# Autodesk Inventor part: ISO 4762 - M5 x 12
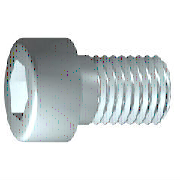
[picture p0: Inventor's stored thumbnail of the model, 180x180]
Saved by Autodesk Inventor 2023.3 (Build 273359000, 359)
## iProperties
Created: 2022-02
Part Number: ISO 4762 - M5 x 12
Material: Acier inoxydable 440C
Description: Vis cylindrique à six pans creux
Document SubType Name: Modeling
Standard: ISO 4762
Designer: Thier
Standard Revision: Fourth edition 2004-03-01
Standards Organization: ISO
Language: fr-FR
Size Designation: M5 x 12
Categories: <MemberInstance><Categories><Category DisplayName="Visserie" InternalName="e4da775c-781d-43d5-af7c-5136215cf5a6" Mnemonic="FSTN"><Category DisplayName="Vis" Int
Density: 7.75 g/cm^3
Appearance: Semi-poli
IsCustomPart: 0
Author: Thier
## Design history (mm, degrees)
sketch "Esquisse1"
  geometry: L1 (-1.167, 0)-(12, 0); L2 (12, 0)-(12, 2.5); L3 (12, 2.5)-(2, 2.5); L4 (2, 2.5)-(1.509, 2.5); L5 (1.509, 2.5)-(0, 2.5); L6 (0, 2.5)-(0, 4.25); L7 (0, 4.25)-(-5, 4.25); L8 (-5, 4.25)-(-5, 2.309); L9 (-5, 2.309)-(-2.5, 2.309); L10 (-2.5, 2.309)-(-1.167, 0); L11 (-8.4, 0)-(15.4, 0) reference; L12 (0, -0.85)-(0, 5.1) reference; L13 (2, 2.5)-(0, 2.5)
  constraints: 22 end point, 6 parallel, 2 collinear, 2 perpendicular, 1 horizontal, 1 point on line
  dimensions: "d1" = 10 distance from line of L3.end L2 (= GEL); "d2" = 0.49086 distance of L4.end L3.end (computed from GAL); "d3" = 5 distance between parallel lines of L8 L6 (= KOH); "d4" = 2.5 distance of L8.end L9.end (= INTI); "d5" = 60 deg angle of L10 L1; "d6" = 5 diameter of L3 L1 (= GD); "d7" = 5 diameter of L5 L1 (= BDM); "d8" = 4.6188 diameter of L9 L1 (= 1.1547 x SW); "d9" = 8.5 diameter of L7 L1 (= KOD); "d26" = 12 distance between parallel lines of L12 L2 (= NLG)
revolve "Corps" sketch "Esquisse1" stored, may be unused: angle "d10" = 90 deg
sketch "Esquisse2"
  geometry: L1 (0, -5.95)-(0, 5.95) reference; L2 (-5.95, 0)-(5.95, 0) reference; L3 (2.309, 0)-(1.155, -2); L4 (1.155, -2)-(-1.155, -2); L5 (-1.155, -2)-(-2.309, 0); L6 (-2.309, 0)-(-1.155, 2); L7 (-1.155, 2)-(1.155, 2); L8 (1.155, 2)-(2.309, 0); 2 further points
  constraints: 12 end point, 1 coincident, 1 horizontal alignment, 1 point on line, 12 other
extrude "Rainure" join sketch "Esquisse2" stored distance "d11" = 10; taper "d12" = 0 deg
workplane "Work Plane1"
fillet "Fillet2" dims "d30" = 0.1 (= R)
body "Solid1"
fillet "Congé1" dims "d17" = 0.5 (= RR)
feature "Filetage" dims "d13" = 10 (= GEL), "d14" = 0
chamfer "Chanfrein1" distance "d15" = 0.49076 (= -0.5 x SPD + 0.5 x GD); stored, may be unused: second distance "d16" = 0.49076 (= GUL), angle "d27" = 45 deg
other parameters: "GD" = 5 [user parameter; used in 2 equation terms], "NLG" = 12 [user parameter; used in 1 equation term], "GEL" = 10 [user parameter; used in 2 equation terms], "KOD" = 8.5 [user parameter; used in 1 equation term], "KOH" = 5 [user parameter; used in 1 equation term], "INTI" = 2.5 [user parameter; used in 1 equation term], "GAL" = 0.49076 (= 0.61345 x PTC) [user parameter; used in 1 equation term], "GUL" = 0.49076 (= 0.61345 x PTC) [user parameter; used in 1 equation term], "BDM" = 5 (= NND) [user parameter; used in 1 equation term], "SW" = 4 [user parameter; used in 2 equation terms], "RR" = 0.5 [user parameter; used in 1 equation term], "SPD" = 4.01848 (= NND - 1.2269 x PTC) [user parameter; used in 1 equation term], "d19" = 0, "d28" = 0, "d29" = 0, "R" = 0.1 [user parameter; used in 1 equation term], "TOA" = 30 deg [user parameter], "GD1" = 4.01848 (= THREADDIA - 1.2269 x PTC) [user parameter], "THREADDIA" = 5 [user parameter; used in 1 equation term], "FAWI" = 45 deg [user parameter], "TPU" = 12.5 (computed from PTC) [user parameter], "PTC" = 0.8 [user parameter; used in 5 equation terms], "NND" = 5 [user parameter; used in 2 equation terms], "E0" = 4.62 (= 1.155 x SW) [user parameter]
